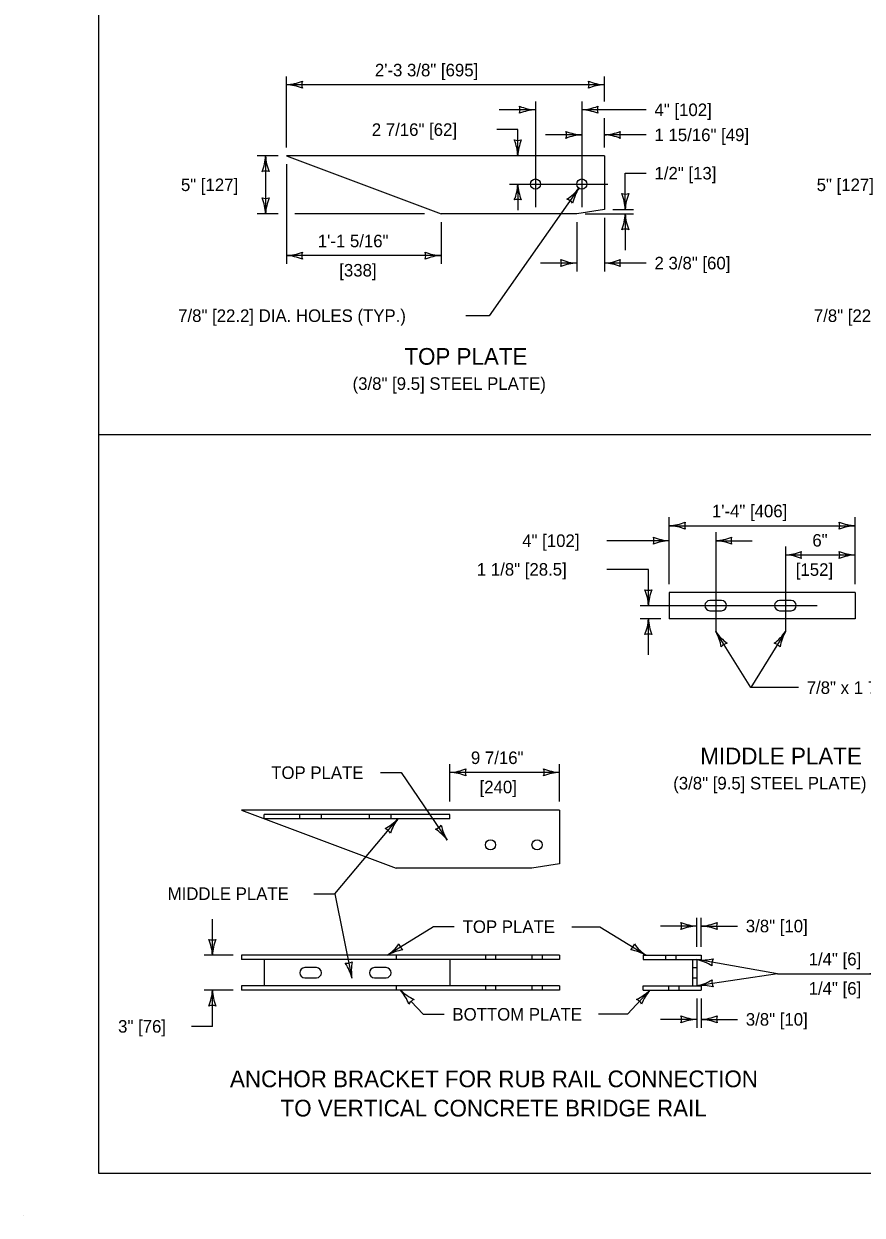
# Model space of a CAD drawing. Extents: x 49991.4 to 50021, y 49987.6 to 50011.4.
# Drawn here: x 49999.02 to 50003.04, y 49987.6 to 49993.3 of the extents above; entities that cross this region are included whole.
import ezdxf

# ---------------------------------------------------------------- set-up
doc = ezdxf.new("R2010")
doc.units = 0
for name, color, linetype in [('Level 1', 7, 'Continuous'), ('Level 2', 7, 'Continuous'), ('Level 3', 7, 'Continuous'), ('Level 4', 7, 'Continuous'), ('Level 5', 7, 'Continuous'), ('Level 7', 7, 'Continuous')]:
    doc.layers.add(name, color=color, linetype=linetype)

msp = doc.modelspace()

# ---------------------------------------------------------------- linework, layer by layer
at = {"layer": 'Level 1'}
for p, q in [((50001.802, 49992.6677), (50000.2812, 49992.6677)), ((50000.2812, 49992.6677), (50001.0208, 49992.39)), ((50001.802, 49992.6677), (50001.802, 49992.4108)), ((50001.802, 49992.4108), (50001.6701, 49992.39)), ((50001.6701, 49992.39), (50001.0208, 49992.39)), ((50005.9232, 49991.3327), (49999.3835, 49991.3327)), ((50003.0018, 49990.5778), (50002.1129, 49990.5778)), ((50002.1129, 49990.5778), (50002.1129, 49990.4528)), ((50002.3629, 49990.5396), (50002.3073, 49990.5396)), ((50002.6962, 49990.5396), (50002.6407, 49990.5396)), ((50003.0018, 49990.5778), (50003.0018, 49990.4528)), ((50002.3073, 49990.491), (50002.3629, 49990.491)), ((50002.6407, 49990.491), (50002.6962, 49990.491)), ((50003.0018, 49990.4528), (50002.1129, 49990.4528)), ((50001.5875, 49989.5374), (50000.0667, 49989.5374)), ((50000.0667, 49989.5374), (50000.8062, 49989.2596)), ((50001.5875, 49989.5374), (50001.5875, 49989.2804)), ((50000.1743, 49989.4957), (50000.1743, 49989.4969)), ((50000.1775, 49989.4957), (50000.1743, 49989.4957)), ((50001.5875, 49989.2804), (50001.4555, 49989.2596)), ((50001.4555, 49989.2596), (50000.8062, 49989.2596)), ((50001.5875, 49988.8422), (50000.0667, 49988.8422)), ((50000.0667, 49988.8422), (50000.0667, 49988.8214)), ((50001.5875, 49988.8214), (50000.0667, 49988.8214)), ((50000.1743, 49988.8214), (50000.1743, 49988.6964)), ((50000.8062, 49988.8422), (50000.8062, 49988.8214)), ((50001.0632, 49988.8214), (50001.0632, 49988.6964)), ((50001.5875, 49988.8422), (50001.5875, 49988.8214)), ((50001.9875, 49988.8422), (50002.2653, 49988.8422)), ((50001.9875, 49988.8422), (50001.9875, 49988.8214)), ((50001.9875, 49988.8214), (50002.2653, 49988.8214)), ((50002.2238, 49988.8214), (50002.2238, 49988.6964)), ((50002.2446, 49988.8214), (50002.2446, 49988.6964)), ((50002.2653, 49988.8422), (50002.2653, 49988.8214)), ((50000.4243, 49988.7832), (50000.3687, 49988.7832)), ((50000.7576, 49988.7832), (50000.7021, 49988.7832)), ((50000.3687, 49988.7346), (50000.4243, 49988.7346)), ((50000.7021, 49988.7346), (50000.7576, 49988.7346)), ((50001.5875, 49988.6964), (50000.0667, 49988.6964)), ((50000.0667, 49988.6964), (50000.0667, 49988.6756)), ((50001.5875, 49988.6756), (50000.0667, 49988.6756)), ((50000.8062, 49988.6964), (50000.8062, 49988.6756)), ((50001.5875, 49988.6964), (50001.5875, 49988.6756)), ((50001.9875, 49988.6964), (50002.2655, 49988.6964)), ((50001.9875, 49988.6756), (50001.9875, 49988.6964)), ((50001.9875, 49988.6756), (50002.2655, 49988.6756)), ((50002.2655, 49988.6964), (50002.2655, 49988.6756)), ((49999.0245, 49987.5988), (49999.0245, 49987.5988))]:
    msp.add_line(p, q, dxfattribs=at)
msp.add_lwpolyline([(49999.3835, 49998.9992), (50016.7501, 49998.9992), (50016.7501, 49987.7988), (49999.3835, 49987.7988)], close=True, dxfattribs=at)
for centre in [(50001.4722, 49992.5323), (50001.6944, 49992.5323), (50001.2576, 49989.3707), (50001.4799, 49989.3707)]:
    msp.add_circle(centre, 0.0243, dxfattribs=at)
for centre, start, end in [((50002.3073, 49990.5153), 90, 270), ((50002.3629, 49990.5153), 270, 90), ((50002.6407, 49990.5153), 90, 270), ((50002.6962, 49990.5153), 270, 90), ((50000.3687, 49988.7589), 90, 270), ((50000.4243, 49988.7589), 270, 90), ((50000.7021, 49988.7589), 90, 270), ((50000.7576, 49988.7589), 270, 90)]:
    msp.add_arc(centre, 0.0243, start, end, dxfattribs=at)
at = {"layer": 'Level 3'}
for p, q in [((50000.2812, 49992.7077), (50000.2812, 49993.0477)), ((50001.802, 49992.9277), (50001.802, 49993.0477)), ((50001.802, 49993.0077), (50000.2812, 49993.0077)), ((50001.4722, 49992.8877), (50001.2987, 49992.8877)), ((50002.002, 49992.8877), (50001.6944, 49992.8877)), ((50001.802, 49992.7077), (50001.802, 49992.8477)), ((50001.3879, 49992.7929), (50001.2879, 49992.7929)), ((50001.3879, 49992.6677), (50001.3879, 49992.7929)), ((50001.6944, 49992.7677), (50001.521, 49992.7677)), ((50002.002, 49992.7677), (50001.802, 49992.7677)), ((50000.2412, 49992.6677), (50000.1412, 49992.6677)), ((50000.1812, 49992.6677), (50000.1812, 49992.39)), ((50000.2812, 49992.6277), (50000.2812, 49992.15)), ((50001.902, 49992.4108), (50001.902, 49992.5842)), ((50001.902, 49992.5842), (50002.002, 49992.5842)), ((50001.3879, 49992.5323), (50001.3879, 49992.4071)), ((50001.842, 49992.4108), (50001.942, 49992.4108)), ((50000.2412, 49992.39), (50000.1412, 49992.39)), ((50000.9408, 49992.39), (50000.3212, 49992.39)), ((50001.7101, 49992.39), (50001.942, 49992.39)), ((50001.802, 49992.3708), (50001.802, 49992.1142)), ((50001.902, 49992.39), (50001.902, 49992.2165)), ((50001.0208, 49992.35), (50001.0208, 49992.15)), ((50001.6701, 49992.35), (50001.6701, 49992.1142)), ((50001.0208, 49992.19), (50000.2812, 49992.19)), ((50001.6701, 49992.1542), (50001.4967, 49992.1542)), ((50002.002, 49992.1542), (50001.802, 49992.1542)), ((50002.1129, 49990.6178), (50002.1129, 49990.9378)), ((50003.0018, 49990.6178), (50003.0018, 49990.9378)), ((50002.1129, 49990.8978), (50003.0018, 49990.8978)), ((50002.1129, 49990.826), (50001.8141, 49990.826)), ((50002.6684, 49990.7578), (50003.0018, 49990.7578)), ((50002.0129, 49990.6887), (50001.8141, 49990.6887)), ((50002.0129, 49990.5153), (50002.0129, 49990.6887)), ((50002.0729, 49990.4528), (50001.9729, 49990.4528)), ((50002.0129, 49990.2794), (50002.0129, 49990.4528)), ((50002.5036, 49990.1228), (50002.3351, 49990.391)), ((50002.6684, 49990.391), (50002.5036, 49990.1228)), ((50002.7302, 49990.1228), (50002.5036, 49990.1228)), ((50001.0632, 49989.5774), (50001.0632, 49989.7574)), ((50001.5875, 49989.5774), (50001.5875, 49989.7574)), ((50001.5875, 49989.7174), (50001.0632, 49989.7174)), ((50000.5122, 49989.1371), (50000.5941, 49988.7331)), ((49999.9267, 49988.8422), (49999.9267, 49989.0157)), ((50002.2446, 49988.8822), (50002.2446, 49989.0222)), ((50002.2655, 49988.8822), (50002.2655, 49989.0222)), ((50002.2446, 49988.9822), (50002.0712, 49988.9822)), ((50002.2655, 49988.9822), (50002.4389, 49988.9822)), ((50000.0267, 49988.8422), (49999.8867, 49988.8422)), ((50002.6298, 49988.7538), (50002.2446, 49988.8214)), ((50002.6298, 49988.7538), (50002.2446, 49988.6964)), ((50000.0267, 49988.6756), (49999.8867, 49988.6756)), ((49999.9267, 49988.5021), (49999.9267, 49988.6756)), ((50002.2446, 49988.6356), (50002.2446, 49988.4956)), ((50002.2655, 49988.6356), (50002.2655, 49988.4956)), ((50002.2446, 49988.5356), (50002.0712, 49988.5356)), ((50002.2655, 49988.5356), (50002.4389, 49988.5356)), ((49999.9267, 49988.5021), (49999.8267, 49988.5021))]:
    msp.add_line(p, q, dxfattribs=at)
for points in [[(50001.6804, 49992.5124), (50001.2505, 49991.9026), (50001.1394, 49991.9026)], [(50000.7303, 49989.7161), (50000.8303, 49989.7161), (50001.0505, 49989.3927)], [(50000.4122, 49989.1371), (50000.5122, 49989.1371), (50000.8147, 49989.4957)], [(50001.0842, 49988.979), (50000.9842, 49988.979), (50000.7637, 49988.8422)], [(50001.6463, 49988.979), (50001.781, 49988.979), (50002.0015, 49988.8422)], [(50002.6298, 49988.7538), (50003.5221, 49988.7538), (50003.0715, 49988.7538)], [(50002.0201, 49988.6756), (50001.912, 49988.5599), (50001.7746, 49988.5599)], [(50000.8772, 49988.6219), (50000.9352, 49988.5599), (50001.0352, 49988.5599)]]:
    msp.add_lwpolyline(points, dxfattribs=at)
for centre, radius, start, end in [((50000.2697, 49993.2405), 0.233, 272.8273, 292.0772), ((50000.272, 49992.7856), 0.2223, 67.456, 87.6395), ((50000.4094, 49993.0077), 0.0548, 162.1388, 197.8612), ((50001.8112, 49993.2299), 0.2223, 247.456, 267.6395), ((50001.6738, 49993.0077), 0.0548, 342.1388, 17.8612), ((50001.8135, 49992.775), 0.233, 92.8273, 112.0772), ((50001.4813, 49993.1099), 0.2223, 247.456, 267.6395), ((50001.344, 49992.8877), 0.0548, 342.1388, 17.8612), ((50001.4837, 49992.655), 0.233, 92.8273, 112.0772), ((50001.6852, 49993.1099), 0.2223, 272.3605, 292.544), ((50001.6829, 49992.655), 0.233, 67.9228, 87.1727), ((50001.8226, 49992.8877), 0.0548, 162.1388, 197.8612), ((50001.7036, 49992.9899), 0.2223, 247.456, 267.6395), ((50001.5662, 49992.7677), 0.0548, 342.1388, 17.8612), ((50001.7059, 49992.535), 0.233, 92.8273, 112.0772), ((50001.7905, 49993.0005), 0.233, 272.8273, 292.0772), ((50001.7929, 49992.5456), 0.2223, 67.456, 87.6395), ((50001.9302, 49992.7677), 0.0548, 162.1388, 197.8612), ((50001.1657, 49992.6586), 0.2223, 2.3605, 22.544), ((50001.3879, 49992.796), 0.0548, 252.1388, 287.8612), ((50001.6206, 49992.6562), 0.233, 157.9228, 177.1727), ((49999.9485, 49992.6792), 0.233, 337.9228, 357.1727), ((50000.4033, 49992.6769), 0.2223, 182.3605, 202.544), ((50000.1812, 49992.5395), 0.0548, 72.1388, 107.8612), ((50001.1657, 49992.5414), 0.2223, 337.456, 357.6395), ((50001.6206, 49992.5438), 0.233, 182.8273, 202.0772), ((49999.9591, 49992.3808), 0.2223, 2.3605, 22.544), ((50000.1812, 49992.5182), 0.0548, 252.1388, 287.8612), ((50000.4139, 49992.3785), 0.233, 157.9228, 177.1727), ((50001.5041, 49992.6479), 0.2223, 302.2723, 322.4558), ((50001.8772, 49992.3877), 0.233, 147.6436, 166.8935), ((50001.6799, 49992.4016), 0.2223, 2.3605, 22.544), ((50001.902, 49992.539), 0.0548, 252.1388, 287.8612), ((50002.1347, 49992.3993), 0.233, 157.9228, 177.1727), ((50001.3879, 49992.4041), 0.0548, 72.1388, 107.8612), ((50001.6065, 49992.4076), 0.0548, 36.9551, 72.6775), ((50001.6799, 49992.3991), 0.2223, 337.456, 357.6395), ((50002.1347, 49992.4015), 0.233, 182.8273, 202.0772), ((50001.902, 49992.2617), 0.0548, 72.1388, 107.8612), ((50000.2697, 49992.4227), 0.233, 272.8273, 292.0772), ((50000.272, 49991.9678), 0.2223, 67.456, 87.6395), ((50000.4094, 49992.19), 0.0548, 162.1388, 197.8612), ((50001.0299, 49992.4121), 0.2223, 247.456, 267.6395), ((50000.8926, 49992.19), 0.0548, 342.1388, 17.8612), ((50001.0323, 49991.9572), 0.233, 92.8273, 112.0772), ((50001.6792, 49992.3763), 0.2223, 247.456, 267.6395), ((50001.5419, 49992.1542), 0.0548, 342.1388, 17.8612), ((50001.6816, 49991.9215), 0.233, 92.8273, 112.0772), ((50001.7929, 49992.3763), 0.2223, 272.3605, 292.544), ((50001.7905, 49991.9215), 0.233, 67.9228, 87.1727), ((50001.9302, 49992.1542), 0.0548, 162.1388, 197.8612), ((50002.1014, 49991.1305), 0.233, 272.8273, 292.0772), ((50002.1037, 49990.6757), 0.2223, 67.456, 87.6395), ((50002.2411, 49990.8978), 0.0548, 162.1388, 197.8612), ((50003.0109, 49991.1199), 0.2223, 247.456, 267.6395), ((50002.8736, 49990.8978), 0.0548, 342.1388, 17.8612), ((50003.0133, 49990.6651), 0.233, 92.8273, 112.0772), ((50002.122, 49991.0481), 0.2223, 247.456, 267.6395), ((50001.9846, 49990.826), 0.0548, 342.1388, 17.8612), ((50002.1243, 49990.5933), 0.233, 92.8273, 112.0772), ((50002.3236, 49991.0587), 0.233, 272.8273, 292.0772), ((50002.3259, 49990.6039), 0.2223, 67.456, 87.6395), ((50002.4633, 49990.826), 0.0548, 162.1388, 197.8612), ((50002.6569, 49990.9905), 0.233, 272.8273, 292.0772), ((50002.6593, 49990.5357), 0.2223, 67.456, 87.6395), ((50002.7966, 49990.7578), 0.0548, 162.1388, 197.8612), ((50003.0109, 49990.9799), 0.2223, 247.456, 267.6395), ((50002.8736, 49990.7578), 0.0548, 342.1388, 17.8612), ((50003.0133, 49990.5251), 0.233, 92.8273, 112.0772), ((50001.7907, 49990.5061), 0.2223, 2.3605, 22.544), ((50002.0129, 49990.6435), 0.0548, 252.1388, 287.8612), ((50002.2456, 49990.5038), 0.233, 157.9228, 177.1727), ((50001.7907, 49990.462), 0.2223, 337.456, 357.6395), ((50002.2456, 49990.4643), 0.233, 182.8273, 202.0772), ((50002.0129, 49990.3246), 0.0548, 72.1388, 107.8612), ((50002.5183, 49990.5169), 0.2223, 214.5034, 234.6869), ((50002.1319, 49990.2769), 0.233, 10.0657, 29.3156), ((50002.4762, 49990.5226), 0.233, 306.3506, 325.6004), ((50002.8625, 49990.2825), 0.2223, 150.7882, 170.9717), ((50002.4033, 49990.2824), 0.0548, 104.2817, 140.0041), ((50002.6013, 49990.2818), 0.0548, 40.5665, 76.2889), ((50001.054, 49989.9395), 0.2223, 272.3605, 292.544), ((50001.1914, 49989.7174), 0.0548, 162.1388, 197.8612), ((50001.4593, 49989.7174), 0.0548, 342.1388, 17.8612), ((50001.599, 49989.9501), 0.233, 247.9228, 267.1727), ((50001.0517, 49989.4846), 0.233, 67.9228, 87.1727), ((50001.5966, 49989.4952), 0.2223, 92.3605, 112.544), ((50000.6508, 49989.6459), 0.2223, 297.3114, 317.4949), ((50000.7321, 49989.3977), 0.0548, 31.9942, 67.7165), ((50001, 49989.3545), 0.233, 142.6827, 161.9325), ((50000.9783, 49989.4987), 0.0548, 286.3802, 322.1025), ((50000.872, 49989.2601), 0.2223, 36.6018, 56.7853), ((50001.2493, 49989.5141), 0.233, 192.1642, 211.414), ((50002.1164, 49988.9822), 0.0548, 342.1388, 17.8612), ((50002.2561, 49989.2149), 0.233, 247.9228, 267.1727), ((50002.254, 49989.2149), 0.233, 272.8273, 292.0772), ((50002.3937, 49988.9822), 0.0548, 162.1388, 197.8612), ((50002.2538, 49988.7601), 0.2223, 92.3605, 112.544), ((50002.2563, 49988.7601), 0.2223, 67.456, 87.6395), ((49999.9267, 49988.9704), 0.0548, 252.1388, 287.8612), ((49999.6939, 49988.8307), 0.233, 2.8273, 22.0772), ((50000.1488, 49988.8331), 0.2223, 157.456, 177.6395), ((50000.6388, 49989.0261), 0.2223, 304.1791, 324.3626), ((50000.8726, 49988.9098), 0.0548, 193.9575, 229.6798), ((50001.8925, 49988.9098), 0.0548, 310.3202, 346.0425), ((50002.1264, 49989.0261), 0.2223, 215.6374, 235.8209), ((50000.8766, 49988.6384), 0.233, 99.7415, 118.9913), ((50001.8886, 49988.6384), 0.233, 61.0087, 80.2585), ((50002.2736, 49989.0526), 0.233, 262.8681, 282.1179), ((50002.1972, 49988.6042), 0.2223, 57.4968, 77.6803), ((50002.3709, 49988.7992), 0.0548, 152.1796, 187.9019), ((50000.5687, 49988.8588), 0.0548, 263.6018, 299.3241), ((50000.3684, 49988.6756), 0.233, 14.2903, 33.5401), ((50000.8137, 49988.7683), 0.2223, 168.919, 189.1025), ((50002.199, 49988.9249), 0.233, 281.2995, 300.5493), ((50002.3714, 49988.7153), 0.0548, 170.611, 206.3334), ((49999.7045, 49988.6847), 0.2223, 337.456, 357.6395), ((50000.1594, 49988.687), 0.233, 182.8273, 202.0772), ((50000.6585, 49988.5305), 0.2223, 20.5277, 40.7112), ((50000.9892, 49988.8429), 0.233, 225.899, 245.1489), ((50001.858, 49988.8429), 0.233, 294.8511, 314.101), ((50002.1887, 49988.5305), 0.2223, 139.2888, 159.4723), ((50002.2683, 49988.4753), 0.2223, 75.9282, 96.1117), ((49999.9267, 49988.5473), 0.0548, 72.1388, 107.8612), ((50000.9146, 49988.5819), 0.0548, 115.2105, 150.9329), ((50001.9326, 49988.5819), 0.0548, 29.0671, 64.7895), ((50002.2538, 49988.7577), 0.2223, 247.456, 267.6395), ((50002.1164, 49988.5356), 0.0548, 342.1388, 17.8612), ((50002.2561, 49988.3028), 0.233, 92.8273, 112.0772), ((50002.2563, 49988.7577), 0.2223, 272.3605, 292.544), ((50002.254, 49988.3028), 0.233, 67.9228, 87.1727), ((50002.3937, 49988.5356), 0.0548, 162.1388, 197.8612)]:
    msp.add_arc(centre, radius, start, end, dxfattribs=at)
at = {"layer": 'Level 4'}
for p, q in [((50000.1743, 49989.4969), (50000.1743, 49989.5166)), ((50001.0632, 49989.5166), (50000.1743, 49989.5166)), ((50000.3444, 49989.4957), (50000.3444, 49989.5166)), ((50000.4486, 49989.4957), (50000.4486, 49989.5166)), ((50000.6778, 49989.4957), (50000.6778, 49989.5166)), ((50000.7819, 49989.4957), (50000.7819, 49989.5166)), ((50001.0632, 49989.4957), (50001.0632, 49989.5166)), ((50001.0632, 49989.4957), (50000.1775, 49989.4957)), ((50001.2333, 49988.8422), (50001.2333, 49988.8214)), ((50001.2819, 49988.8422), (50001.2819, 49988.8214)), ((50001.4555, 49988.8422), (50001.4555, 49988.8214)), ((50001.5042, 49988.8422), (50001.5042, 49988.8214)), ((50002.0952, 49988.8422), (50002.0952, 49988.8214)), ((50002.1439, 49988.8422), (50002.1439, 49988.8214)), ((50002.2238, 49988.7832), (50002.2446, 49988.7832)), ((50002.2238, 49988.7346), (50002.2446, 49988.7346)), ((50001.2333, 49988.6964), (50001.2333, 49988.6756)), ((50001.2819, 49988.6964), (50001.2819, 49988.6756)), ((50001.4555, 49988.6964), (50001.4555, 49988.6756)), ((50001.5042, 49988.6964), (50001.5042, 49988.6756)), ((50002.1092, 49988.6964), (50002.1092, 49988.6756)), ((50002.1579, 49988.6964), (50002.1579, 49988.6756))]:
    msp.add_line(p, q, dxfattribs=at)
at = {"layer": 'Level 5'}
for p, q in [((50001.4722, 49992.9277), (50001.4722, 49992.4219)), ((50001.6944, 49992.9277), (50001.6944, 49992.4219)), ((50001.3479, 49992.5323), (50001.8187, 49992.5323)), ((50002.3351, 49990.866), (50002.3351, 49990.391)), ((50002.6684, 49990.7978), (50002.6684, 49990.391)), ((50001.9729, 49990.5153), (50002.8205, 49990.5153))]:
    msp.add_line(p, q, dxfattribs=at)
at = {"layer": 'Level 7'}
msp.add_line((50002.3351, 49990.826), (50002.5085, 49990.826), dxfattribs=at)

# ---------------------------------------------------------------- texts
at = {"layer": 'Level 2'}
for s, p in [('2\'-3 3/8" [695]', (50000.7043, 49993.0477)), ('4" [102]', (50002.042, 49992.8577)), ('2 7/16" [62]', (50000.6895, 49992.7629)), ('1 15/16" [49]', (50002.042, 49992.7377)), ('1/2" [13]', (50002.042, 49992.5542)), ('5" [127]', (49999.7762, 49992.4988)), ('5" [127]', (50002.8179, 49992.4988)), ('1\'-1 5/16"', (50000.4312, 49992.23)), ('2 3/8" [60]', (50002.042, 49992.1242)), ('[338]', (50000.5338, 49992.09)), ('7/8" [22.2] DIA. HOLES (TYP.)', (49999.7628, 49991.8726)), ('7/8" [22.2] DIA. HOLES (TYP.)', (50002.8044, 49991.8726)), ('(3/8" [9.5] STEEL PLATE)', (50000.5974, 49991.5477)), ('1\'-4" [406]', (50002.3167, 49990.9378)), ('4" [102]', (50001.4092, 49990.796)), ('6"', (50002.7971, 49990.7978)), ('1 1/8" [28.5]', (50001.1921, 49990.6587)), ('[152]', (50002.718, 49990.6578)), ('7/8" x 1 7/8" [22.2 x 47.6] SLOTS', (50002.7702, 49990.0928)), ('9 7/16"', (50001.1637, 49989.7574)), ('TOP PLATE', (50000.2082, 49989.6861)), ('[240]', (50001.2052, 49989.6174)), ('(3/8" [9.5] STEEL PLATE)', (50002.1315, 49989.6358)), ('MIDDLE PLATE', (49999.7127, 49989.1071)), ('TOP PLATE', (50001.1242, 49988.949)), ('3/8" [10]', (50002.4789, 49988.9522)), ('1/4" [6]', (50002.7796, 49988.7938)), ('1/4" [6]', (50002.7796, 49988.6538)), ('BOTTOM PLATE', (50001.0752, 49988.5299)), ('3/8" [10]', (50002.4789, 49988.5056))]:
    msp.add_text(s, height=0.06, rotation=360, dxfattribs=at).set_placement(p)
for s, height, p in [('TOP PLATE', 0.08, (50000.8453, 49991.6677)), ('MIDDLE PLATE', 0.08, (50002.2611, 49989.7558)), ('3" [76]', 0.06, (49999.4756, 49988.4721)), ('ANCHOR BRACKET FOR RUB RAIL CONNECTION', 0.08, (50000.0108, 49988.211)), ('TO VERTICAL CONCRETE BRIDGE RAIL', 0.08, (50000.2529, 49988.071))]:
    msp.add_text(s, height=height, dxfattribs=at).set_placement(p)

doc.saveas('drawing.dxf')
